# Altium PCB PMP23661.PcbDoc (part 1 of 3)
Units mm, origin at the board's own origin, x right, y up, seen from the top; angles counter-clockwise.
Board outline 209 x 127 mm, 4 copper layers (Top Layer, Layer 1, Layer 2, Bottom Layer), stack 1.787 mm thick; 235 components, 114 nets, 814 pads, 405 vias.
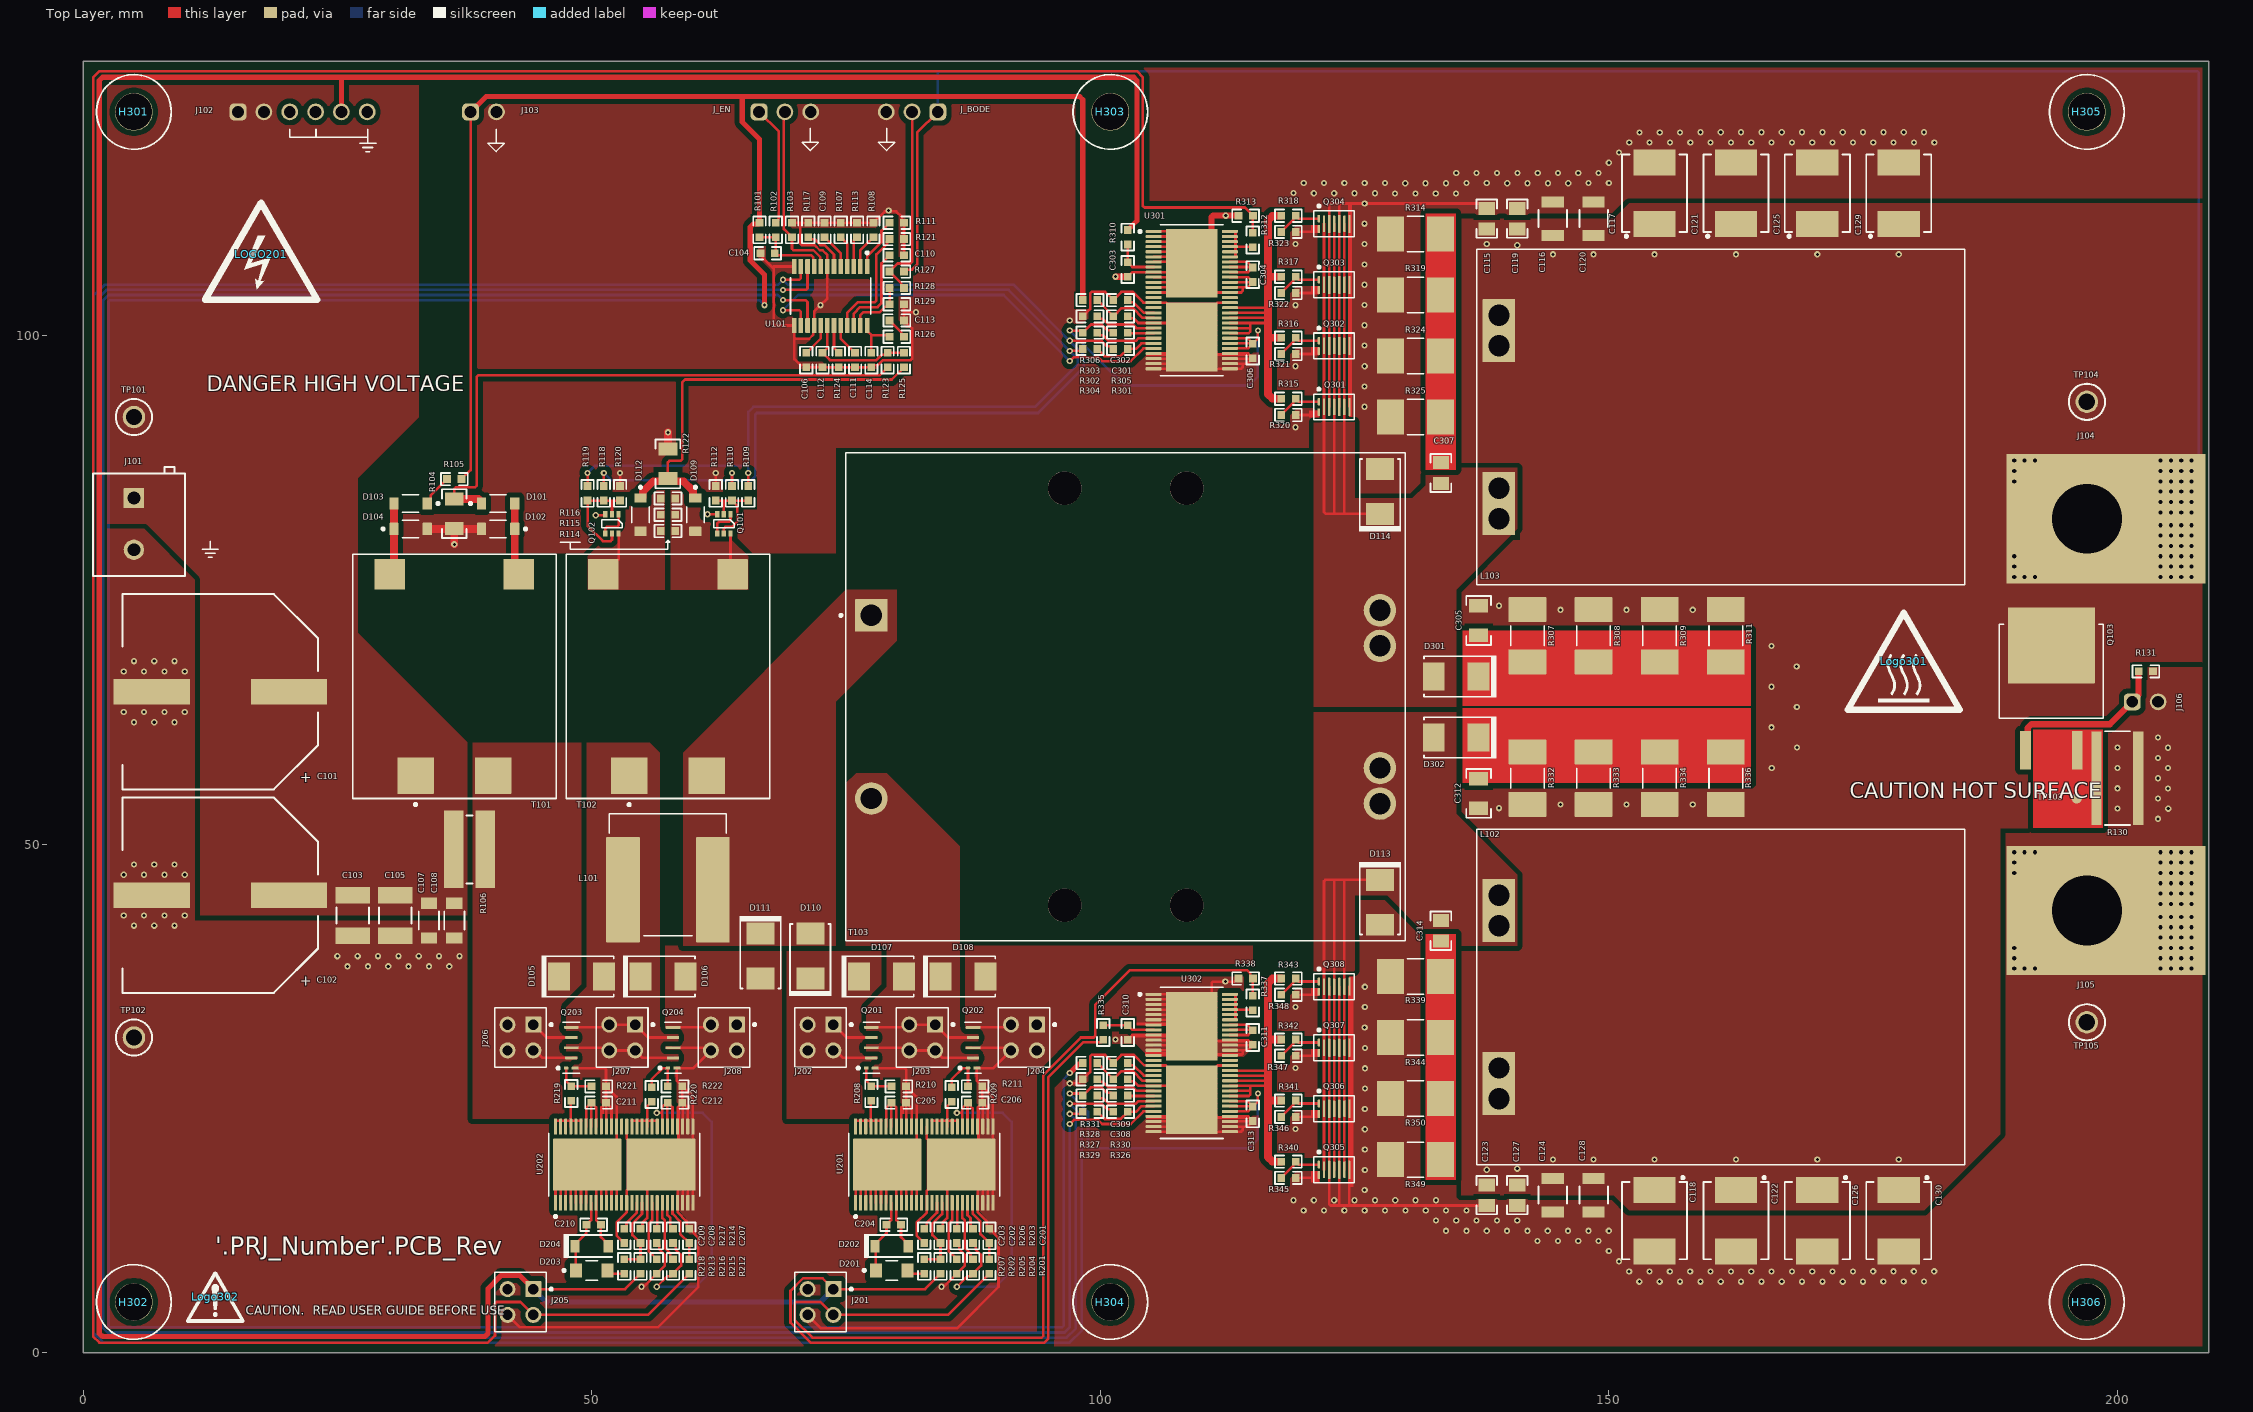
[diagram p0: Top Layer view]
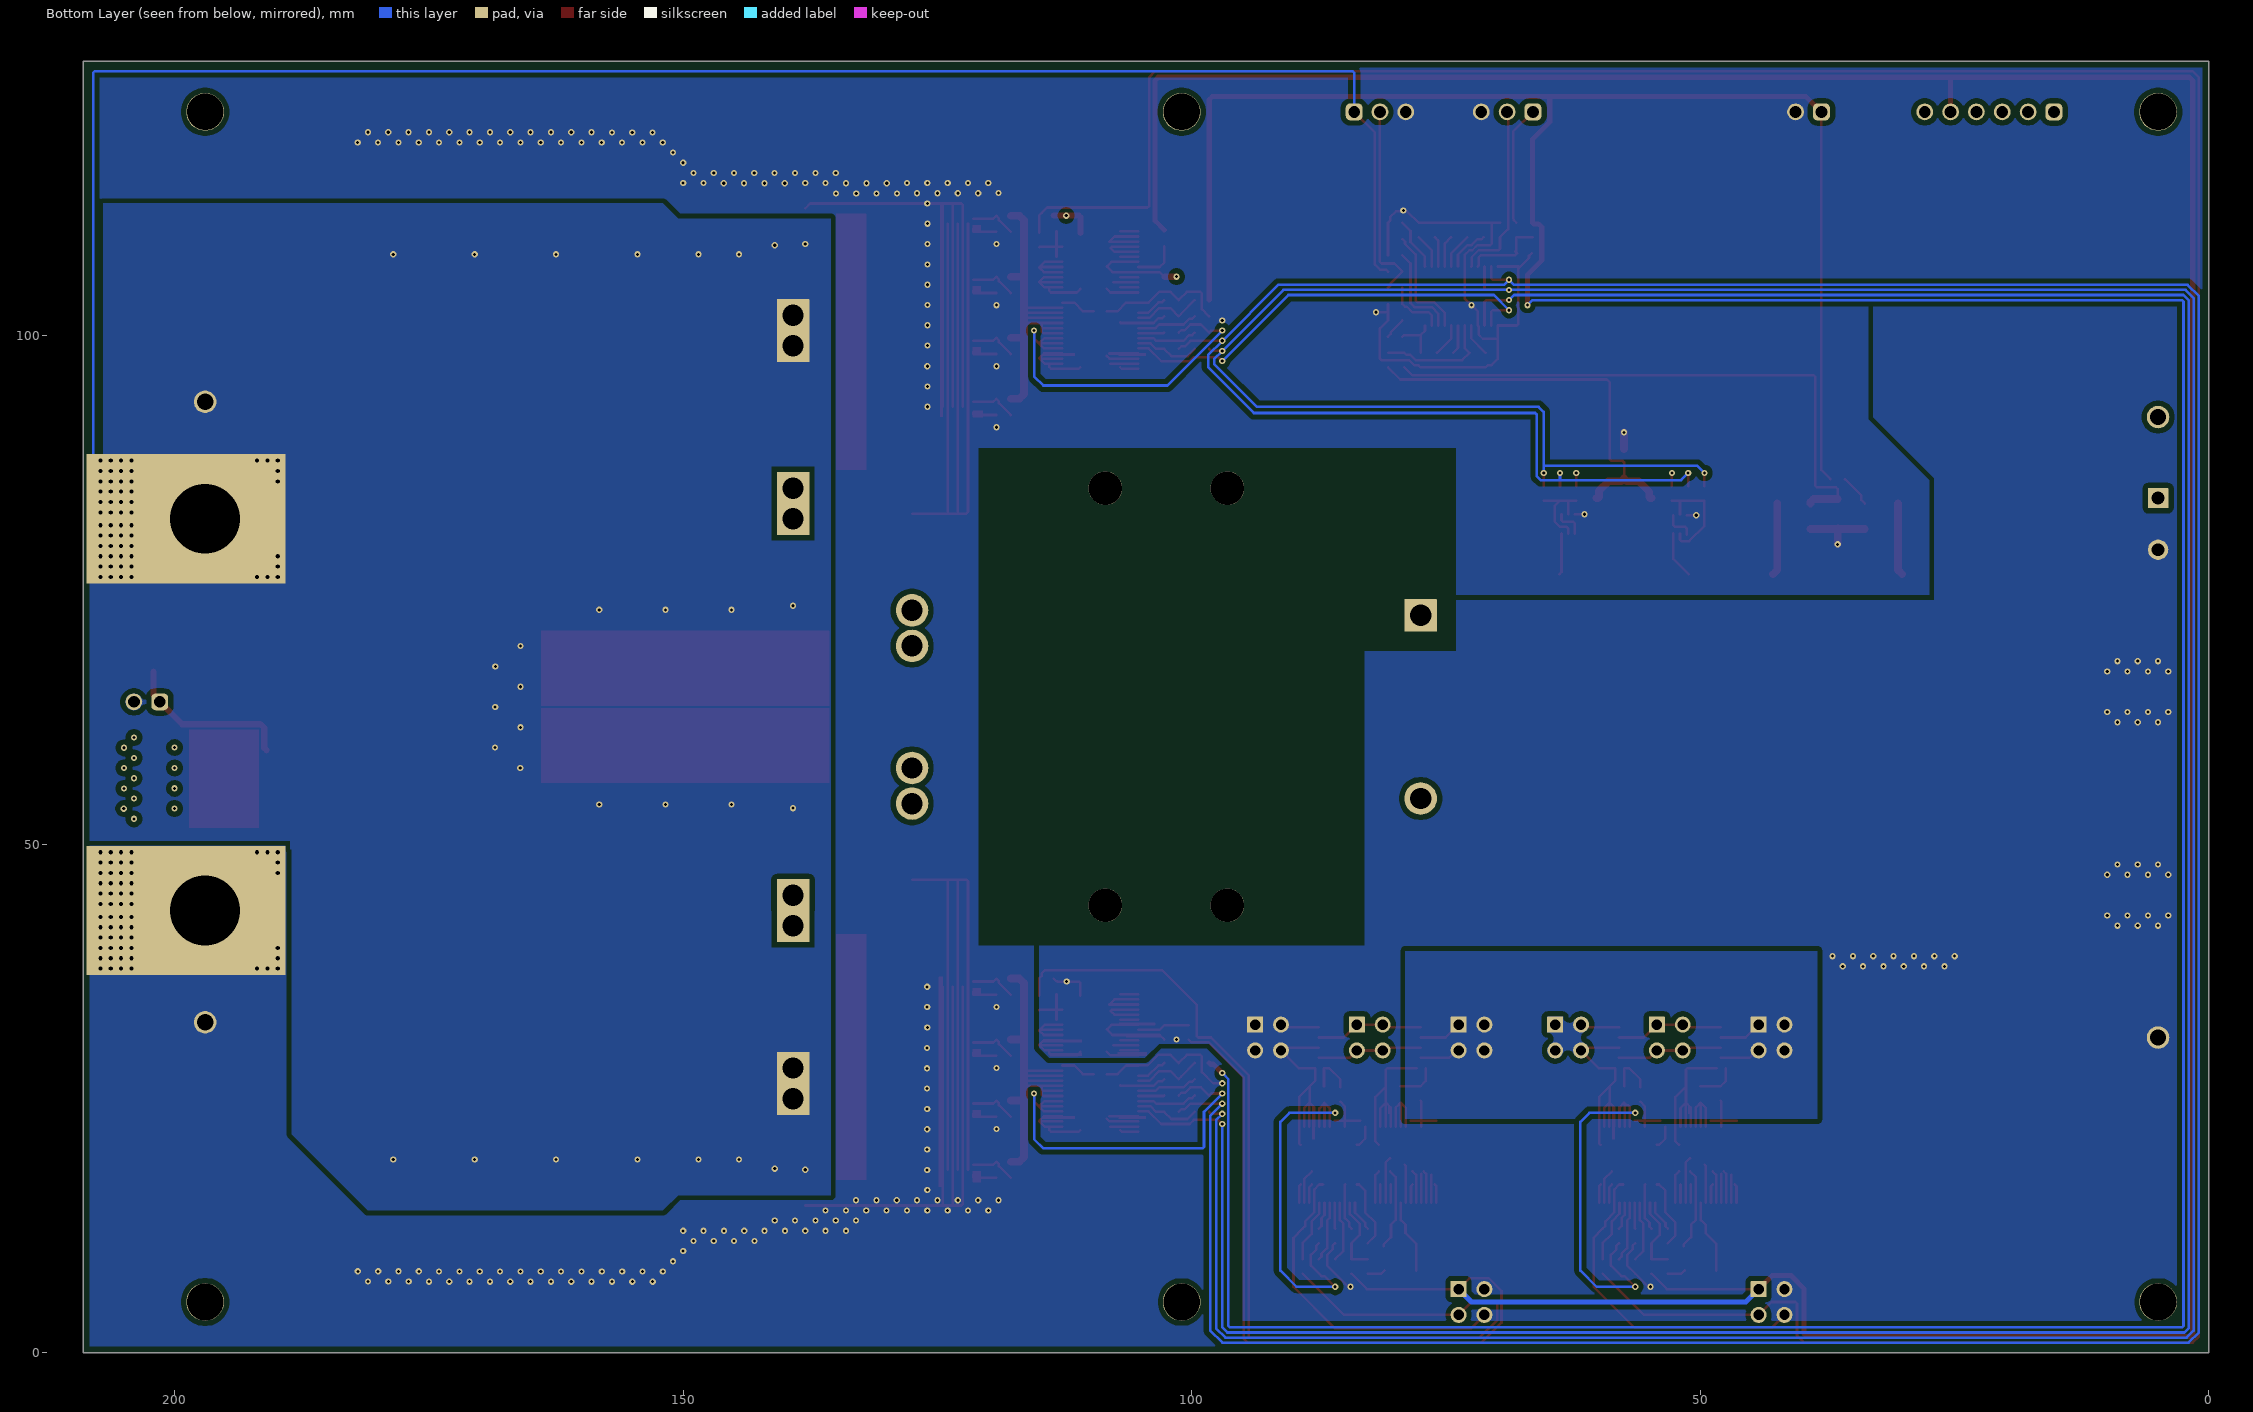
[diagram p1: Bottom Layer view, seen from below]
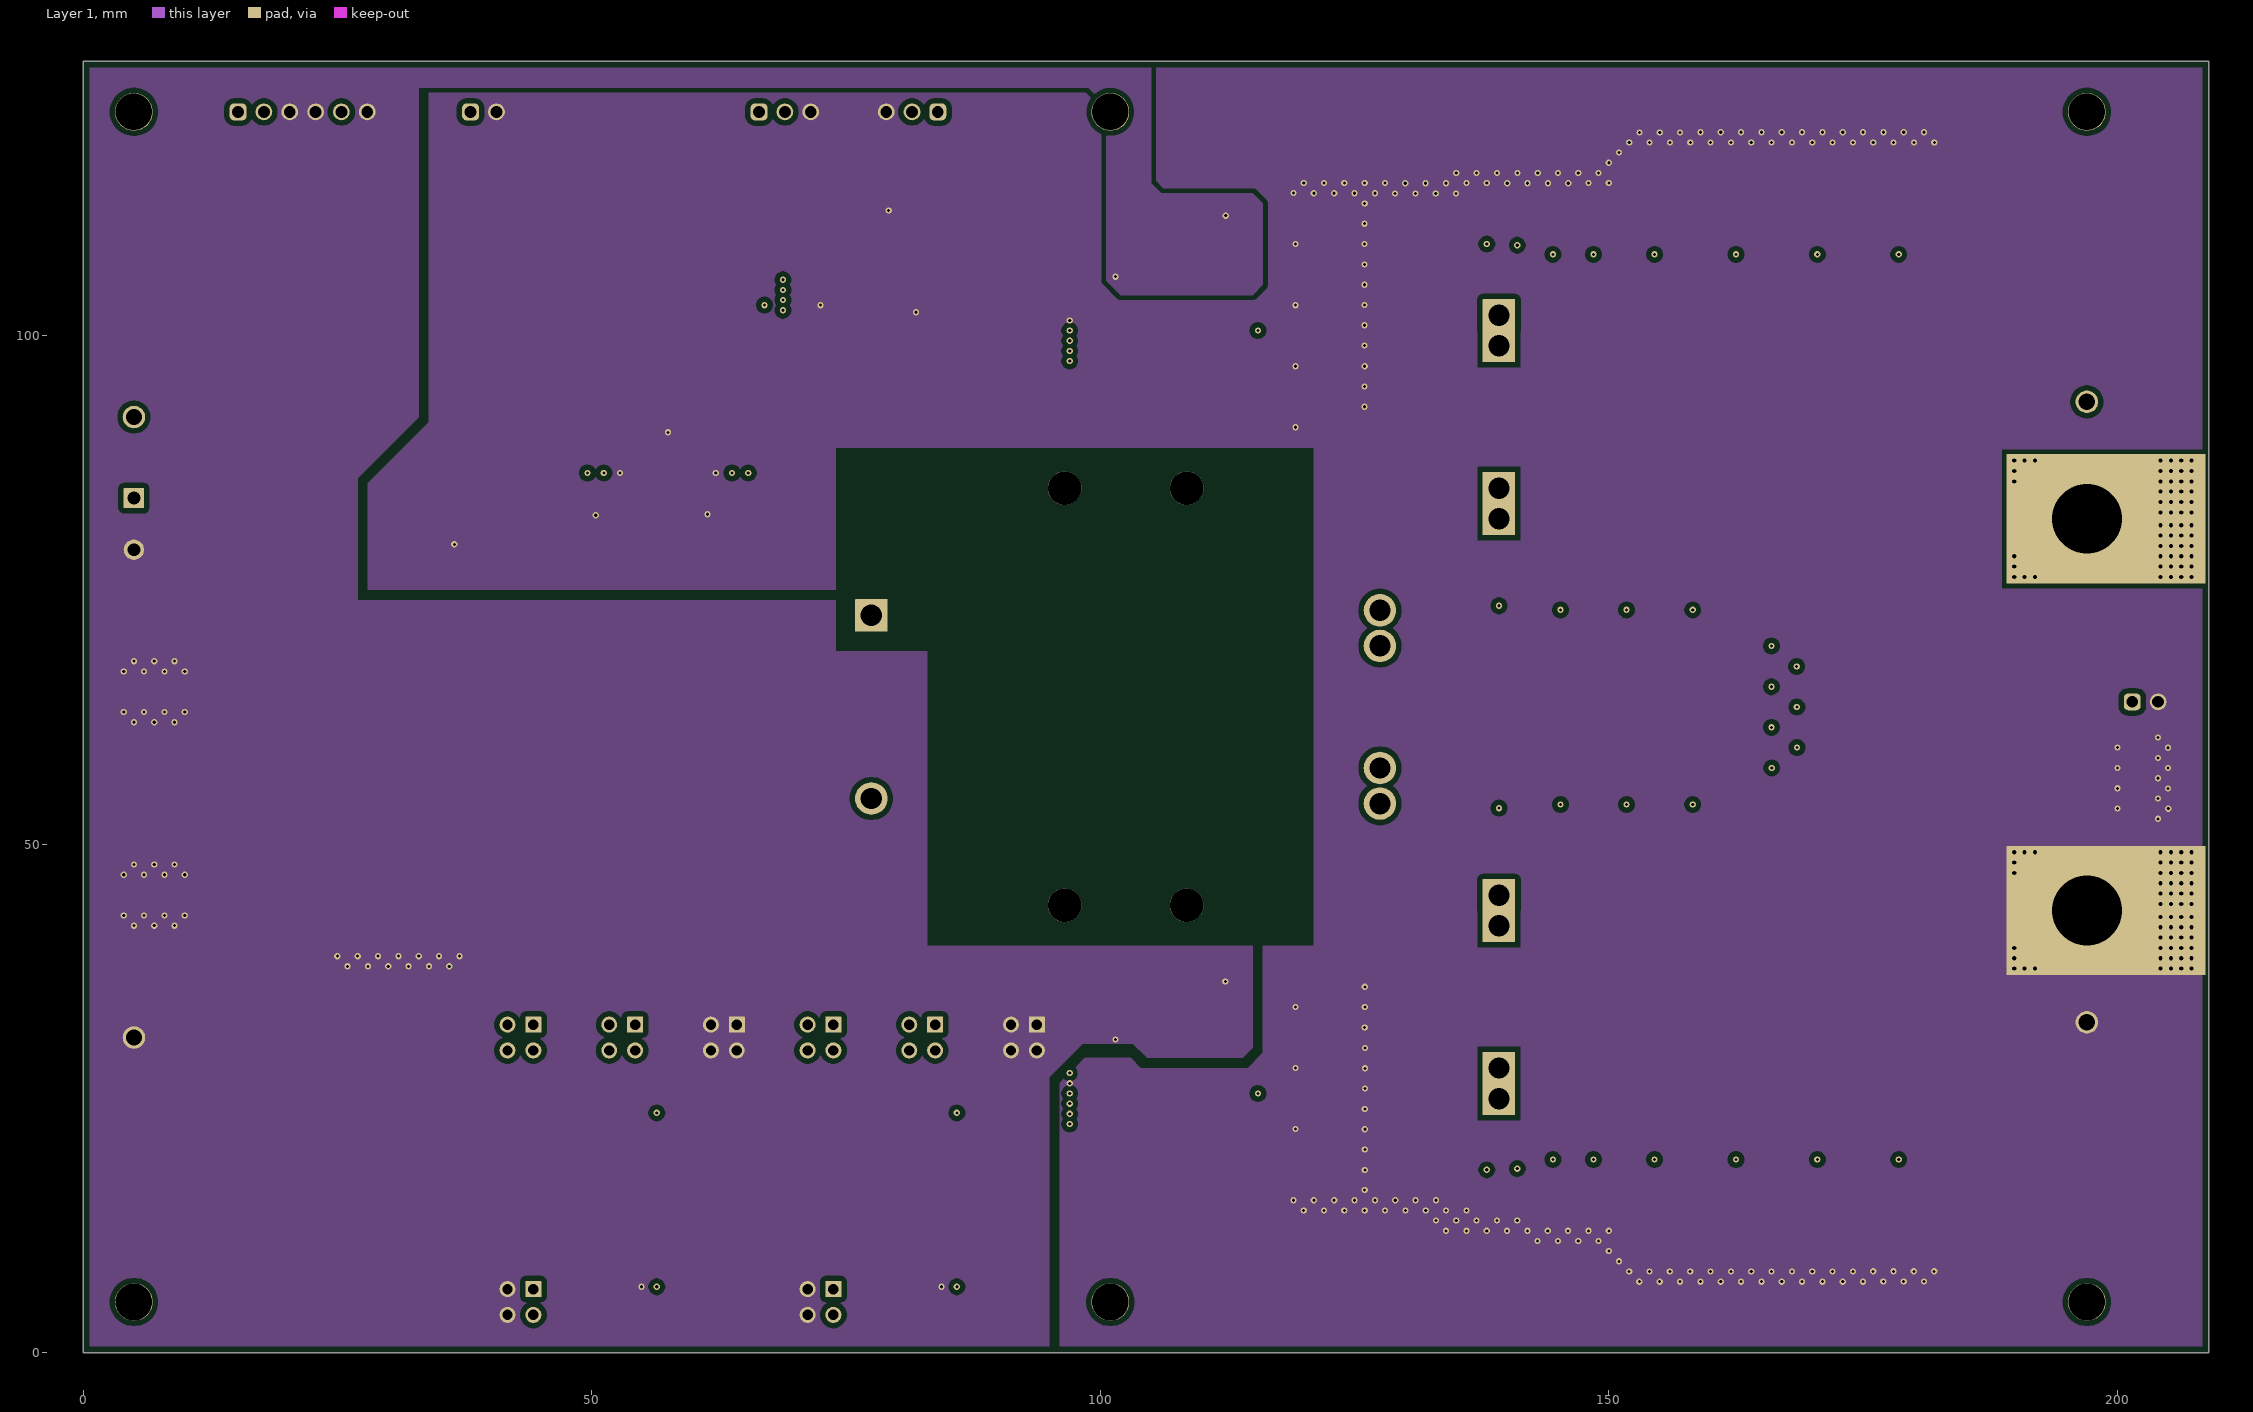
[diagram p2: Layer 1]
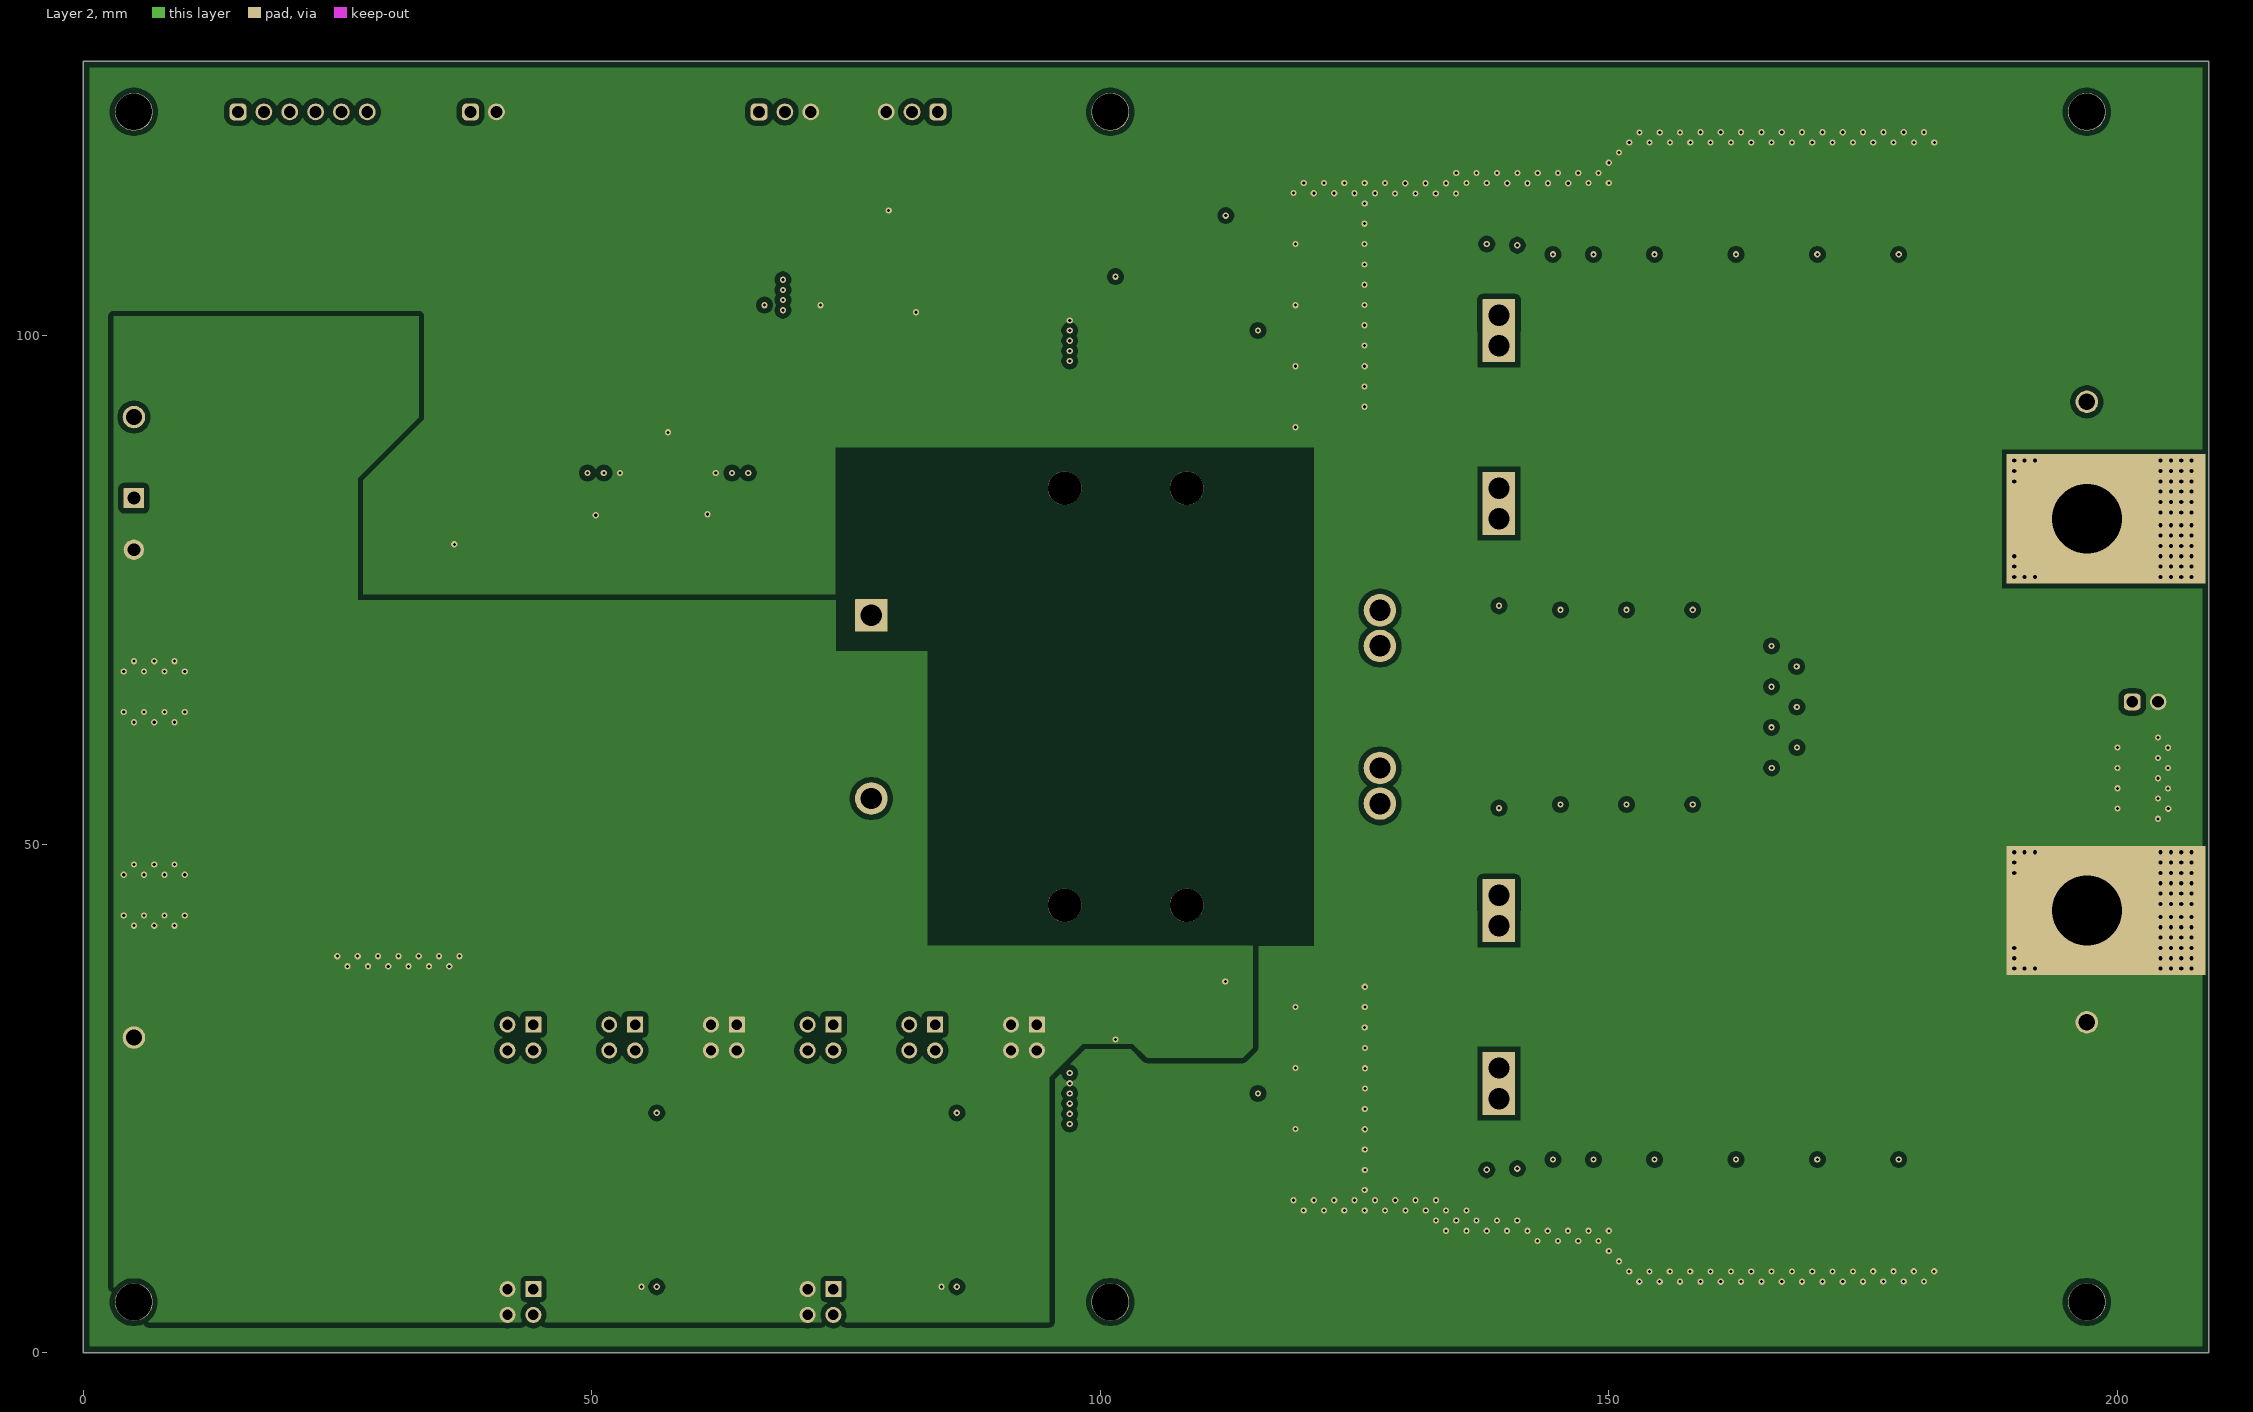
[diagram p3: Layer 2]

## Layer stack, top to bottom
Top Solder: solder mask 0.0102, Solder Resist, Dk 3.5
Top Layer: signal copper 0.0356
Dielectric 1: prepreg 0.0711, PP-006, Dk 4.1
Layer 1: signal copper 0.035
Dielectric1: core 1.5037, FR-4 High Tg, Dk 4.8
Layer 2: signal copper 0.035
Dielectric 2: prepreg 0.0711, PP-006, Dk 4.1
Bottom Layer: signal copper 0.0356
Bottom Solder: solder mask 0.0102, Solder Resist, Dk 3.5

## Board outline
0,0 0,127 209,127 209,0

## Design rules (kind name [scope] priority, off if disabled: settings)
AcuteAngle [All] p1: minimum=4.50000000000000E+0001 checktracksonly=FALSE
AssemblyTestPointUsage [All] p1: valid=2
BoardOutlineClearance BoardOutlineClearance_MountingHoles [OnCopper and InComponentClass('Mounting Holes')] p1: gap=0.635 ignorepadtopadclearanceinfootprint=FALSE
BoardOutlineClearance BoardOutlineClearance_Poly [OnCopper and InPoly] p2: gap=0.635 ignorepadtopadclearanceinfootprint=FALSE
BoardOutlineClearance [OnCopper and Not InComponentClass('Logo') and not InComponentClass('FiducialMark') and not InRegion(1000,500,4000,800)] p3: gap=0.635 ignorepadtopadclearanceinfootprint=FALSE
Clearance Clearance_2 [InNetClass('HV') vs Not InNetClass('HV')] p1: gap=1.524 ignorepadtopadclearanceinfootprint=FALSE
Clearance Clearance_1 [InNetClass('MV') vs Not InNetClass('MV')] p2: gap=0.762 ignorepadtopadclearanceinfootprint=FALSE
Clearance Clearance_Keepouts [((IsTrack Or IsArc) And Not InPoly) And IsFree and IsKeepOut vs ((IsTrack Or IsArc) And Not InPoly) And IsFree and IsKeepOut] p3: gap=0 ignorepadtopadclearanceinfootprint=FALSE
Clearance Clearance_BoardEdge_MountingHoles [OnCopper and InComponentClass('Mounting Holes') vs IsKeepOut] p4: gap=1.016 ignorepadtopadclearanceinfootprint=FALSE except(0: Arc-Hole Track-Hole SMDPad-Hole THPad-Hole Via-Hole Fill-Hole Poly-Hole Region-Hole Text-Hole)
Clearance Clearance_BoardEdge_Poly [OnCopper and InPoly vs IsKeepOut] p5: gap=1.27 ignorepadtopadclearanceinfootprint=FALSE except(0: Arc-Hole Track-Hole SMDPad-Hole THPad-Hole Via-Hole Fill-Hole Poly-Hole Region-Hole Text-Hole)
Clearance Clearance_BoardEdge [OnCopper and Not InComponentClass('Logo') and not InComponentClass('FiducialMark') and not InRegion(1000,500,4000,800) and Not IsKeepout vs IsKeepOut] p6: gap=1.27 ignorepadtopadclearanceinfootprint=FALSE
Clearance Clearance_Poly [InPolygon] p7: gap=0.508 ignorepadtopadclearanceinfootprint=FALSE except(0: Arc-Hole Track-Hole SMDPad-Hole THPad-Hole Via-Hole Fill-Hole Poly-Hole Region-Hole Text-Hole)
Clearance [All] p8: gap=0.152 ignorepadtopadclearanceinfootprint=FALSE
ComponentClearance ComponentClearance_MountingHoles_FiducialMarks [InComponentClass('Mounting Holes') vs InComponentClass('FiducialMark')] p1: gap=0.508 collisioncheckmode=3 verticalgap=0.254 showdistances=FALSE
ComponentClearance ComponentClearance_Shunt [InComponentClass('Header') vs InComponentClass('Shunt')] p2: gap=0 collisioncheckmode=3 verticalgap=0 showdistances=FALSE
ComponentClearance ComponentClearance_Logo [InComponentClass('Logo')] p3: gap=0.127 collisioncheckmode=3 verticalgap=0.254 showdistances=FALSE
ComponentClearance ComponentClearance_ScrewToNut [(HasFootprint('NY PMS 440 0025 PH')) vs (HasFootprint('Keystone_1902C'))] p4: gap=0.508 collisioncheckmode=3 verticalgap=2540 showdistances=FALSE
ComponentClearance ComponentClearance_MountingHoles [InComponentClass('Mounting Holes')] p5: gap=0.508 collisioncheckmode=3 verticalgap=0.254 showdistances=FALSE
ComponentClearance ComponentClearance_SmallPassives [HasFootprint('0201*') or HasFootprint('0402*') or HasFootprint('0508') or HasFootprint('0603*') or HasFootprint('0612') or HasFootprint('0805*') or HasFootprint('0815*') or HasFootprint('0830*') or HasFootprint('1206*') or HasFootprint('1210*') or HasFootprint('1808*') or HasFootprint('1812*') or HasFootprint('1825*') or HasFootprint('2010*') or HasFootprint('2220*') or HasFootprint('2225*') or HasFootprint('2512*') or HasFootprint('2728*') or HasFootprint('3518*') vs HasFootprint('0201*') or HasFootprint('0402*') or HasFootprint('0508') or HasFootprint('0603*') or HasFootprint('0612') or HasFootprint('0805*') or HasFootprint('0815*') or HasFootprint('0830*') or HasFootprint('1206*') or HasFootprint('1210*') or HasFootprint('1808*') or HasFootprint('1812*') or HasFootprint('1825*') or HasFootprint('2010*') or HasFootprint('2220*') or HasFootprint('2225*') or HasFootprint('2512*') or HasFootprint('2728*') or HasFootprint('3518*')] p6: gap=0.508 collisioncheckmode=3 verticalgap=0.508 showdistances=FALSE
ComponentClearance ComponentClearance_THtoSMT [IsThruComponent vs IsSMTComponent] p7: gap=0.254 collisioncheckmode=3 verticalgap=0.254 showdistances=FALSE
ComponentClearance ComponentClearance_THtoTH [IsThruComponent vs IsThruComponent] p8: gap=0.254 collisioncheckmode=3 verticalgap=0.254 showdistances=FALSE
ComponentClearance [All] p9: gap=0.254 collisioncheckmode=3 verticalgap=0.254 showdistances=FALSE
DiffPairsRouting [All] p1: maxlimit=2.54 minlimit=0.254 mostfreqgap=0.254 toplayer_minwidth=0.381 toplayer_maxwidth=0.381 toplayer_prefwidth=0.381 midlayer1_minwidth=0.381 midlayer1_maxwidth=0.381 midlayer1_prefwidth=0.381 midlayer2_minwidth=0.381 midlayer2_maxwidth=0.381 midlayer2_prefwidth=0.381 bottomlayer_minwidth=0.381 bottomlayer_maxwidth=0.381 bottomlayer_prefwidth=0.381 maxuncoupledlength=25.4
FabricationTestPointUsage TestPointUsage [All] p1: valid=2 allowmultiple=FALSE
FabricationTestpoint Testpoint [All] p1: side=3 testpointundercomponent=TRUE minsize=1.016 maxsize=2.54 preferedsize=1.524 minholesize=0 maxholesize=1.016 preferedholesize=0.813 testpointgrid=0.025 allowsidetop=TRUE allowsidebottom=TRUE usegrid=TRUE gridtolerance=0
FanoutControl Fanout_LCC [IsLCC] p1: bgadir=Out bgaviamode=Centered fanoutstyle=Auto fanoutdirection=Alternating viagrid=0.025 // Fanout_LCC (Default Rule)
FanoutControl Fanout_BGA [IsBGA] p2: bgadir=Out bgaviamode=Centered fanoutstyle=Auto fanoutdirection=Alternating viagrid=0.025 // Fanout_BGA (Default Rule)
FanoutControl Fanout_Default [All] p4: bgadir=Out bgaviamode=Centered fanoutstyle=Auto fanoutdirection=Alternating viagrid=0.025 // Fanout_Default (Default Rule)
FanoutControl Fanout_Small [(CompPinCount < 5)] p5: bgadir=Out bgaviamode=Centered fanoutstyle=Auto fanoutdirection=OutThenIn viagrid=0.025 // Fanout_Small (Default Rule)
Height [All] p1: minheight=0 maxheight=76.2 prefheight=12.7
HoleSize [All] p1: absolutevalues=TRUE maxlimit=6.375 minlimit=0.2 maxpercent=80.000 minpercent=20.000
MinimumAnnularRing MinimumAnnularRing_ThermalPadVias [IsVia and InAnyComponent] p1: minimumring=0.15
MinimumAnnularRing [All] p2: minimumring=0.15
MinimumSolderMaskSliver MinimumSolderMaskSliver_Logo [InComponentClass('Logo') vs InComponentClass('Logo')] p1: minsoldermaskwidth=0.018
MinimumSolderMaskSliver [All] p2: minsoldermaskwidth=0.1
PlaneConnect [All] p1: planeconnectstyle=Direct reliefexpansion=0.254 reliefentries=4 reliefconductorwidth=0.254 reliefairgap=0.254
PolygonConnect PolygonConnect_15 [All vs IsNamedPolygon('C109_2') Or  IsNamedPolygon('C107_2') Or  IsNamedPolygon('HV') Or  IsNamedPolygon('Q203_5') Or  IsNamedPolygon('C107_2') Or  IsNamedPolygon('HS') Or  IsNamedPolygon('Q201_5') Or  IsNamedPolygon('Q203_5') Or  IsNamedPolygon('C106_2') Or  IsNamedPolygon('C108_2') Or  IsNamedPolygon('Vout') Or  IsNamedPolygon('Q203_5') Or  IsNamedPolygon('C108_2') Or  IsNamedPolygon('C113_2') Or  IsNamedPolygon('Q203_5') Or  IsNamedPolygon('Q201_5') Or  IsNamedPolygon('C107_2') Or  IsNamedPolygon('C102_1') Or  IsNamedPolygon('SGND') Or  IsNamedPolygon('GND') Or  IsNamedPolygon('SGND') Or  IsNamedPolygon('GND') Or  IsNamedPolygon('IN+') Or  IsNamedPolygon('IN+') Or  IsNamedPolygon('Q201_5') Or  IsNamedPolygon('Q201_5') Or  IsNamedPolygon('SGND') Or  IsNamedPolygon('SGND') Or  IsNamedPolygon('Vout') Or  IsNamedPolygon('Vout') Or  IsNamedPolygon('IN+') Or  IsNamedPolygon('GND') Or  IsNamedPolygon('IN+') Or  IsNamedPolygon('GND')] p1: connectstyle=Direct reliefconductorwidth=0.254 reliefentries=4 polygonreliefangle="90 Angle" airgapwidth=0.254
PolygonConnect PolygonConnect_14 [All vs IsNamedPolygon('C106_2') Or  IsNamedPolygon('C107_2') Or  IsNamedPolygon('C107_2') Or  IsNamedPolygon('C107_2') Or  IsNamedPolygon('C102_1') Or  IsNamedPolygon('Q203_5') Or  IsNamedPolygon('Vout') Or  IsNamedPolygon('Q203_5') Or  IsNamedPolygon('Q203_5') Or  IsNamedPolygon('Q201_5') Or  IsNamedPolygon('C108_2') Or  IsNamedPolygon('Q203_5') Or  IsNamedPolygon('HS') Or  IsNamedPolygon('HV') Or  IsNamedPolygon('C108_2') Or  IsNamedPolygon('Q201_5') Or  IsNamedPolygon('C109_2') Or  IsNamedPolygon('Q201_5') Or  IsNamedPolygon('Q201_5') Or  IsNamedPolygon('C113_2')] p2: connectstyle=Direct reliefconductorwidth=0.254 reliefentries=4 polygonreliefangle="90 Angle" airgapwidth=0.254
PolygonConnect PolygonConnect_13 [All vs IsNamedPolygon('C102_1') Or  IsNamedPolygon('HV') Or  IsNamedPolygon('C107_2') Or  IsNamedPolygon('C109_2') Or  IsNamedPolygon('C107_2') Or  IsNamedPolygon('C108_2') Or  IsNamedPolygon('C106_2') Or  IsNamedPolygon('C108_2') Or  IsNamedPolygon('C113_2') Or  IsNamedPolygon('C107_2')] p3: connectstyle=Direct reliefconductorwidth=0.254 reliefentries=4 polygonreliefangle="90 Angle" airgapwidth=0.254
PolygonConnect PolygonConnect_12 [All vs IsNamedPolygon('C107_2') Or  IsNamedPolygon('C113_2') Or  IsNamedPolygon('C106_2') Or  IsNamedPolygon('C107_2') Or  IsNamedPolygon('C107_2') Or  IsNamedPolygon('C102_1')] p4: connectstyle=Direct reliefconductorwidth=0.254 reliefentries=4 polygonreliefangle="90 Angle" airgapwidth=0.254
PolygonConnect PolygonConnect_11 [All vs IsNamedPolygon('C106_2') Or  IsNamedPolygon('C102_1') Or  IsNamedPolygon('C107_2') Or  IsNamedPolygon('C107_2') Or  IsNamedPolygon('C107_2')] p5: connectstyle=Direct reliefconductorwidth=0.254 reliefentries=4 polygonreliefangle="90 Angle" airgapwidth=0.254
PolygonConnect PolygonConnect_10 [All vs IsNamedPolygon('C106_2')] p6: connectstyle=Direct reliefconductorwidth=0.254 reliefentries=4 polygonreliefangle="90 Angle" airgapwidth=0.254
PolygonConnect PolygonConnect_9 [All vs IsNamedPolygon('C11_1') Or  IsNamedPolygon('Vin') Or  IsNamedPolygon('Vin') Or  IsNamedPolygon('5V') Or  IsNamedPolygon('D6_2') Or  IsNamedPolygon('Q3_3') Or  IsNamedPolygon('GND2') Or  IsNamedPolygon('GND2') Or  IsNamedPolygon('GND') Or  IsNamedPolygon('Q3_4') Or  IsNamedPolygon('12V5') Or  IsNamedPolygon('GND') Or  IsNamedPolygon('12V5') Or  IsNamedPolygon('D3_1')] p7: connectstyle=Direct reliefconductorwidth=0.254 reliefentries=4 polygonreliefangle="90 Angle" airgapwidth=0.254
PolygonConnect PolygonConnect_8 [All vs IsNamedPolygon('C11_1') Or  IsNamedPolygon('Vin') Or  IsNamedPolygon('12V5') Or  IsNamedPolygon('Q3_3') Or  IsNamedPolygon('GND2') Or  IsNamedPolygon('GND2') Or  IsNamedPolygon('5V') Or  IsNamedPolygon('Q3_4') Or  IsNamedPolygon('12V5')] p8: connectstyle=Direct reliefconductorwidth=0.254 reliefentries=4 polygonreliefangle="90 Angle" airgapwidth=0.254
PolygonConnect PolygonConnect_7 [All vs IsNamedPolygon('GND2') Or  IsNamedPolygon('GND2') Or  IsNamedPolygon('5V') Or  IsNamedPolygon('12V5') Or  IsNamedPolygon('12V5') Or  IsNamedPolygon('C11_1')] p9: connectstyle=Direct reliefconductorwidth=0.254 reliefentries=4 polygonreliefangle="90 Angle" airgapwidth=0.254
PolygonConnect PolygonConnect_6 [All vs IsNamedPolygon('GND2') Or  IsNamedPolygon('SGND') Or  IsNamedPolygon('GND1') Or  IsNamedPolygon('C901_1') Or  IsNamedPolygon('SGND') Or  IsNamedPolygon('GND2') Or  IsNamedPolygon('GND1')] p10: connectstyle=Direct reliefconductorwidth=0.254 reliefentries=4 polygonreliefangle="90 Angle" airgapwidth=0.254
PolygonConnect PolygonConnect_5 [All vs IsNamedPolygon('GND1') Or  IsNamedPolygon('GND1')] p11: connectstyle=Direct reliefconductorwidth=0.254 reliefentries=4 polygonreliefangle="90 Angle" airgapwidth=0.254
PolygonConnect PolygonConnect_4 [All vs IsNamedPolygon('C21_1') Or  IsNamedPolygon('C5_1') Or  IsNamedPolygon('C12_2') Or  IsNamedPolygon('C2_2') Or  IsNamedPolygon('C13_1') Or  IsNamedPolygon('C28_1') Or  IsNamedPolygon('C6_1') Or  IsNamedPolygon('GND') Or  IsNamedPolygon('GND2') Or  IsNamedPolygon('C14_1') Or  IsNamedPolygon('C13_1') Or  IsNamedPolygon('Q1_3') Or  IsNamedPolygon('C14_1') Or  IsNamedPolygon('C5_1') Or  IsNamedPolygon('GND2') Or  IsNamedPolygon('C28_1') Or  IsNamedPolygon('D5_2') Or  IsNamedPolygon('D6_2') Or  IsNamedPolygon('D2_1') Or  IsNamedPolygon('C12_2') Or  IsNamedPolygon('D2_1') Or  IsNamedPolygon('C4_1') Or  IsNamedPolygon('C4_1') Or  IsNamedPolygon('C2_2') Or  IsNamedPolygon('GND') Or  IsNamedPolygon('C33_1') Or  IsNamedPolygon('C9_1')] p12: connectstyle=Direct reliefconductorwidth=0.254 reliefentries=4 polygonreliefangle="90 Angle" airgapwidth=0.254
PolygonConnect PolygonConnect_3 [All vs IsNamedPolygon('C28_1') Or  IsNamedPolygon('C12_2') Or  IsNamedPolygon('C28_1') Or  IsNamedPolygon('C9_1') Or  IsNamedPolygon('D5_2') Or  IsNamedPolygon('C12_2') Or  IsNamedPolygon('C2_2') Or  IsNamedPolygon('C14_1') Or  IsNamedPolygon('C4_1') Or  IsNamedPolygon('C14_1') Or  IsNamedPolygon('D6_2') Or  IsNamedPolygon('GND2') Or  IsNamedPolygon('Q1_3') Or  IsNamedPolygon('C5_1') Or  IsNamedPolygon('D2_1') Or  IsNamedPolygon('C4_1') Or  IsNamedPolygon('C13_1') Or  IsNamedPolygon('C5_1') Or  IsNamedPolygon('C13_1') Or  IsNamedPolygon('C33_1') Or  IsNamedPolygon('D2_1') Or  IsNamedPolygon('GND') Or  IsNamedPolygon('GND') Or  IsNamedPolygon('GND2') Or  IsNamedPolygon('C2_2') Or  IsNamedPolygon('C6_1') Or  IsNamedPolygon('C21_1')] p13: connectstyle=Direct reliefconductorwidth=0.254 reliefentries=4 polygonreliefangle="90 Angle" airgapwidth=0.254
PolygonConnect PolygonConnect_2 [All vs IsNamedPolygon('C21_1') Or  IsNamedPolygon('C4_1') Or  IsNamedPolygon('D5_2') Or  IsNamedPolygon('C5_1') Or  IsNamedPolygon('C14_1') Or  IsNamedPolygon('C13_1') Or  IsNamedPolygon('C4_1') Or  IsNamedPolygon('C33_1') Or  IsNamedPolygon('C12_2') Or  IsNamedPolygon('D2_1') Or  IsNamedPolygon('C2_2') Or  IsNamedPolygon('C28_1') Or  IsNamedPolygon('C12_2') Or  IsNamedPolygon('D2_1') Or  IsNamedPolygon('C5_1') Or  IsNamedPolygon('Q1_3') Or  IsNamedPolygon('GND') Or  IsNamedPolygon('D6_2') Or  IsNamedPolygon('C6_1') Or  IsNamedPolygon('C2_2') Or  IsNamedPolygon('C14_1') Or  IsNamedPolygon('C28_1') Or  IsNamedPolygon('C13_1') Or  IsNamedPolygon('C9_1') Or  IsNamedPolygon('GND')] p14: connectstyle=Direct reliefconductorwidth=0.254 reliefentries=4 polygonreliefangle="90 Angle" airgapwidth=0.254
PolygonConnect PolygonConnect_1 [All vs IsNamedPolygon('C28_1') Or  IsNamedPolygon('D5_2') Or  IsNamedPolygon('C5_1') Or  IsNamedPolygon('C5_1') Or  IsNamedPolygon('D2_1') Or  IsNamedPolygon('C21_1') Or  IsNamedPolygon('C9_1') Or  IsNamedPolygon('C4_1') Or  IsNamedPolygon('C14_1') Or  IsNamedPolygon('C28_1') Or  IsNamedPolygon('C6_1') Or  IsNamedPolygon('C12_2') Or  IsNamedPolygon('C33_1') Or  IsNamedPolygon('C4_1') Or  IsNamedPolygon('C13_1') Or  IsNamedPolygon('C12_2') Or  IsNamedPolygon('D6_2') Or  IsNamedPolygon('C2_2') Or  IsNamedPolygon('C14_1') Or  IsNamedPolygon('D2_1') Or  IsNamedPolygon('C2_2') Or  IsNamedPolygon('C13_1')] p15: connectstyle=Direct reliefconductorwidth=0.254 reliefentries=4 polygonreliefangle="90 Angle" airgapwidth=0.254
PolygonConnect [All] p16: connectstyle=Direct reliefconductorwidth=0.254 reliefentries=4 polygonreliefangle="90 Angle" airgapwidth=0.254
RoutingVias ThermalPadVias [IsVia and InAnyComponent] p1: holewidth=0.3 width=0.5 viastyle="Through Hole" minholewidth=0.13 minwidth=0.15 maxholewidth=1 maxwidth=2
RoutingVias [All] p2: holewidth=0.3 width=0.4 viastyle="Through Hole" minholewidth=0.13 minwidth=0.15 maxholewidth=3 maxwidth=6.3
SilkToBoardRegionClearance [Not ((IsComment or IsDesignator) And (Hide <> 'False')) and not InRegion(1000,500,4000,800)] p1:
SilkToSilkClearance SilkToSilkClearance_Pb-FreeLogo [(HasFootprint('Pb-Free_Overlay_Medium') OR HasFootprint('Pb-Free_Overlay_Small')) vs (HasFootprint('Pb-Free_Overlay_Medium') OR HasFootprint('Pb-Free_Overlay_Small'))] p1: silktosilkclearance=0
SilkToSilkClearance [All] p2: silktosilkclearance=0.102
SilkToSolderMaskClearance SilkToComponentPadClearance [IsPad and InAnycomponent] p1: minsilkscreentomaskgap=0.127 clearancetoexposedcopper=TRUE
SilkToSolderMaskClearance "Silk to Solder Mask Opening" [All] p2: minsilkscreentomaskgap=0.102 clearancetoexposedcopper=FALSE
SolderMaskExpansion [All] p1: expansion=0.05 istentingtop=FALSE
SupplyNets "Schematic Supply Nets_7" [InNet('HV')] p1: voltage=0.000
SupplyNets "Schematic Supply Nets_6" [InNet('+12Vs')] p2: voltage=0.000
SupplyNets "Schematic Supply Nets_5" [InNet('PGND')] p3: voltage=0.000
SupplyNets "Schematic Supply Nets_4" [InNet('SGND')] p4: voltage=0.000
SupplyNets "Schematic Supply Nets_1" [InNet('VOUT')] p5: voltage=0.000
SupplyNets "Schematic Supply Nets" [InNet('+12Vp')] p6: voltage=0.000
Width [All] p1: maxlimit=2.54 minlimit=0.152 preferedwidth=0.254 checkconnectedcopper=TRUE
14 further rules are at their usual default settings.

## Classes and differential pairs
component class "PMP23661_Secondary Drivers": !PCB201 C303 C304 C305 C307 C308 C310 C313 D301 D302 H301 H302 H305 H306 Logo301 Logo302 Q301 Q302 Q304 Q308 R303 R305 R306 R310 R312 R314 R316 R317 R321 R324 R326 R327 R330 R334 R338 R339 R342 R345 R347 R349 U301 U302
component class "PMP23661_Primary Drivers": C201 C205 C207 C211 C212 D201 D202 D203 D204 J201 J203 J206 J208 LOGO201 Q201 Q202 Q204 R202 R203 R208 R210 R212 R216 R217 R218 R220 R221 R222 U201 U202
component class Header: J101 J103 J106 J_BODE J_EN

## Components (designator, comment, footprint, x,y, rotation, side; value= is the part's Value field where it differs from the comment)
C101 "EEV-EB2D470SM" EB_K16 13.5,65 r180 top value=47uF
C102 "EEV-EB2D470SM" EB_K16 13.5,45 r180 top value=47uF
C103 "18122C105KAT2A" 1812_280 26.5,43 r270 top value=1uF
C104 "GRM188R71E105KA12D" 0603_HV 67.3,108.1 r180 top value=1uF
C105 "18122C105KAT2A" 1812_280 30.7,43 r270 top value=1uF
C106 "GRM188Z71C225KE43" 0603_HV 71.1,97.6 r90 top value=2.2uF
C107 "GRM31CR72D104KW03L" 1206_180 34,42.5 r270 top value=0.1uF
C108 "GRM31CR72D104KW03L" 1206_180 36.5,42.5 r270 top value=0.1uF
C109 "GRM188R71E562KA01D" 0603_HV 72.9,110.4 r270 top value=5600pF
C110 "GCM188R71E104KA57D" 0603_HV 80,107.9 r0 top value=0.1uF
C111 "GCM188R71C474KA55D" 0603_HV 75.9,97.6 r90 top value=0.47uF
C112 "GCM1885C2A100JA16D" 0603_HV 72.7,97.6 r270 top value=10pF
C113 "GRM188R71E123KA01D" 0603_HV 80,101.5 r0 top value=0.012uF
C114 "GRM188R71H471KA01D" 0603_HV 77.5,97.6 r270 top value=470pF
C115 "C0805C105K3RACTU" 0805_HV 138,111.5 r90 top value=1uF
C116 "C1210C106K3RACTU" 1210_280 144.5,111.5 r90 top value=10uF
C117 "T495E107K025ATE100" 7360-38 154.5,114 r90 top value=100uF
C118 "T495E107K025ATE100" 7360-38 154.5,13 r270 top value=100uF
C119 "C0805C105K3RACTU" 0805_HV 141,111.5 r90 top value=1uF
C120 "C1210C106K3RACTU" 1210_280 148.5,111.5 r90 top value=10uF
C121 "T495E107K025ATE100" 7360-38 162.5,114 r90 top value=100uF
C122 "T495E107K025ATE100" 7360-38 162.5,13 r270 top value=100uF
C123 "C0805C105K3RACTU" 0805_HV 138,15.5 r270 top value=1uF
C124 "C1210C106K3RACTU" 1210_280 144.5,15.5 r270 top value=10uF
C125 "T495E107K025ATE100" 7360-38 170.5,114 r90 top value=100uF
C126 "T495E107K025ATE100" 7360-38 170.5,13 r270 top value=100uF
C127 "C0805C105K3RACTU" 0805_HV 141,15.5 r270 top value=1uF
C128 "C1210C106K3RACTU" 1210_280 148.5,15.5 r270 top value=10uF
C129 "T495E107K025ATE100" 7360-38 178.5,114 r90 top value=100uF
C130 "T495E107K025ATE100" 7360-38 178.5,13 r270 top value=100uF
C201 "GRM1885C1H101JA01D" 0603_HV 89.1,11.5 r90 top value=100pF
C202 "GRM188R71E105KA12D" 0603_HV 84.3,11.5 r90 top value=1uF
C203 "GRM188R71E105KA12D" 0603_HV 82.7,11.5 r90 top value=1uF
C204 "C0603C104K5RACAUTO" 0603_HV 79.7,12.6 r180 top value=0.1uF
C205 "GRM188R71E105KA12D" 0603_HV 80.2,24.6 r180 top value=1uF
C206 "GRM188Z71C225KE43" 0603_HV 87.7,24.6 r180 top value=2.2uF
C207 "GRM1885C1H101JA01D" 0603_HV 59.6,11.5 r270 top value=100pF
C208 "GRM188R71E105KA12D" 0603_HV 54.8,11.5 r90 top value=1uF
C209 "GRM188R71E105KA12D" 0603_HV 53.2,11.5 r90 top value=1uF
C210 "C0603C104K5RACAUTO" 0603_HV 50.2,12.6 r180 top value=0.1uF
C211 "GRM188R71E105KA12D" 0603_HV 50.7,24.6 r180 top value=1uF
C212 "GRM188Z71C225KE43" 0603_HV 58.2,24.6 r180 top value=2.2uF
C301 "GRM188R71E105KA12D" 0603_HV 102,101.9 r0 top value=1uF
C302 "GRM188R71E105KA12D" 0603_HV 102,103.5 r0 top value=1uF
C303 "C0603C104K5RACAUTO" 0603_HV 102.7,106.5 r90 top value=0.1uF
C304 "GRM188Z71C225KE43" 0603_HV 115,106 r90 top value=2.2uF
C305 "GRM319R72A104KA01D" 1206 137.2,72 r90 top value=0.1uF
C306 "GRM188Z71C225KE43" 0603_HV 115,98.5 r90 top value=2.2uF
C307 "GRM2165C2A122JA01D" 0805_HV 133.5,86.5 r90 top value=1200pF
C308 "GRM188R71E105KA12D" 0603_HV 102,26.9 r0 top value=1uF
C309 "GRM188R71E105KA12D" 0603_HV 102,28.5 r0 top value=1uF
C310 "C0603C104K5RACAUTO" 0603_HV 102.7,31.5 r90 top value=0.1uF
C311 "GRM188Z71C225KE43" 0603_HV 115,31 r90 top value=2.2uF
C312 "GRM319R72A104KA01D" 1206 137.2,55 r270 top value=0.1uF
C313 "GRM188Z71C225KE43" 0603_HV 115,23.5 r90 top value=2.2uF
C314 "GRM2165C2A122JA01D" 0805_HV 133.5,41.5 r270 top value=1200pF
D101 "BAT46GWJ" FP-BAT46GWJ_SOD-123-MFG 40.8,83.5 r0 top
D102 "BAT46GWJ" FP-BAT46GWJ_SOD-123-MFG 40.8,81 r180 top
D103 "BAT46GWJ" FP-BAT46GWJ_SOD-123-MFG 32.2,83.5 r180 top
D104 "BAT46GWJ" FP-BAT46GWJ_SOD-123-MFG 32.2,81 r0 top
D105 "MBRS3200T3G" SMB 49,37 r0 top value=200V
D106 "MBRS3200T3G" SMB 57,37 r0 top value=200V
D107 "MBRS3200T3G" SMB 78.5,37 r0 top value=200V
D108 "MBRS3200T3G" SMB 86.5,37 r0 top value=200V
D109 "BAT46GWJ" FP-BAT46GWJ_SOD-123-MFG 60.2,82.4 r270 top
D110 "MBRS3200T3G" SMB 71.5,39 r90 top value=200V
D111 "MBRS3200T3G" SMB 66.6,39 r270 top value=200V
D112 "BAT46GWJ" FP-BAT46GWJ_SOD-123-MFG 54.8,82.4 r270 top
D113 "MBRS1100T3G" SMB 127.5,44.3 r270 top value=100V
D114 "MBRS1100T3G" SMB 127.5,84.7 r90 top value=100V
D201 "SS1H20LW" FP-SS1H20LW_SOD-123W-MFG 79.5,8.1 r0 top
D202 "MMSZ5243B-7-F" SOD-123 79.5,10.5 r0 top value=13V
D203 "SS1H20LW" FP-SS1H20LW_SOD-123W-MFG 50,8.1 r0 top
D204 "MMSZ5243B-7-F" SOD-123 50,10.5 r0 top value=13V
D301 "MBRS1100T3G" SMB 135,66.5 r180 top value=100V
D302 "MBRS1100T3G" SMB 135,60.5 r180 top value=100V
H301 "4820" KEYSTONE_4820 5,122 r0 top
H302 "4820" KEYSTONE_4820 5,5 r0 top
H303 "4820" KEYSTONE_4820 101,122 r0 top
H304 "4820" KEYSTONE_4820 101,5 r0 top
H305 "4820" KEYSTONE_4820 197,122 r0 top
H306 "4820" KEYSTONE_4820 197,5 r0 top
J101 "ED120/2DS" On-Shore_ED120_2DS 5,81.5 r270 top
J102 "61300611121" WURTH_61300611121 21.59,122 r0 top
J103 "61300211121" WURTH_61300211121 39.37,122 r0 top
J104 "CXS70-14-C" Panduit_CXS70-14-C 197,82 r180 top
J105 "CXS70-14-C" Panduit_CXS70-14-C 197,43.5 r180 top
J106 "61300211121" WURTH_61300211121 202.73,64 r0 top
J201 "SSQ-102-02-G-D" FP-SSQ-102-02-G-D_CONN_RCPT_4-MFG 72.5,5 r90 top
J202 "SSQ-102-02-G-D" FP-SSQ-102-02-G-D_CONN_RCPT_4-MFG 72.5,31 r90 top
J203 "SSQ-102-02-G-D" FP-SSQ-102-02-G-D_CONN_RCPT_4-MFG 82.5,31 r90 top
J204 "SSQ-102-02-G-D" FP-SSQ-102-02-G-D_CONN_RCPT_4-MFG 92.5,31 r90 top
J205 "SSQ-102-02-G-D" FP-SSQ-102-02-G-D_CONN_RCPT_4-MFG 43,5 r90 top
J206 "SSQ-102-02-G-D" FP-SSQ-102-02-G-D_CONN_RCPT_4-MFG 43,31 r90 top
J207 "SSQ-102-02-G-D" FP-SSQ-102-02-G-D_CONN_RCPT_4-MFG 53,31 r90 top
J208 "SSQ-102-02-G-D" FP-SSQ-102-02-G-D_CONN_RCPT_4-MFG 63,31 r90 top
J_BODE "61300311121" WURTH_61300311121 81.5,122 r180 top
J_EN "61300311121" WURTH_61300311121 69,122 r0 top
L101 "1212VS-111MED" FP-1212VS-111MED_SMT_IND_11MM5_12MM0-MFG 57.5,47 r0 top value=117nH
L102 "64192R00" FP-64192R00_PTH_IND_48MM0_33MM0-MFG 161,35 r0 top value=2uH
L103 "64192R00" FP-64192R00_PTH_IND_48MM0_33MM0-MFG 161,92 r0 top value=2uH
LOGO201 "DANGER HIGH VOLTAGE" IEC_HighVoltage_Medium 17.5,108 r0 top
Logo301 "CAUTION HOT SURFACE" IEC_HotSurface_Medium 179,68 r0 top
Logo302 "CAUTION.  READ USER GUIDE BEFORE USE" IEC_Caution_Small 13,5.5 r0 top
Q101 "2N7002DW" SOT-363 63,81.5 r270 top value=60V
Q102 "2N7002DW" SOT-363 52,81.5 r270 top value=60V
Q103 "CSD18511KTT" KTT0002A-MFG 193.5,67 r0 top
Q201 "EPC2215" FP-EPC2215_LGA6-MFG 77.5,30 r90 top
Q202 "EPC2215" FP-EPC2215_LGA6-MFG 87.5,30 r90 top
Q203 "EPC2215" FP-EPC2215_LGA6-MFG 48,30 r90 top
Q204 "EPC2215" FP-EPC2215_LGA6-MFG 58,30 r90 top
Q301 "EPC2088" FP-EPC2088_LGA8-MFG 123,93 r0 top
Q302 "EPC2088" FP-EPC2088_LGA8-MFG 123,99 r0 top
Q303 "EPC2088" FP-EPC2088_LGA8-MFG 123,105 r0 top
Q304 "EPC2088" FP-EPC2088_LGA8-MFG 123,111 r0 top
Q305 "EPC2088" FP-EPC2088_LGA8-MFG 123,18 r0 top
Q306 "EPC2088" FP-EPC2088_LGA8-MFG 123,24 r0 top
Q307 "EPC2088" FP-EPC2088_LGA8-MFG 123,30 r0 top
Q308 "EPC2088" FP-EPC2088_LGA8-MFG 123,36 r0 top
R101 "CRCW06030000Z0EA" 0603_HV 66.5,110.4 r90 top value=0
R102 "CRCW060349K9FKEA" 0603_HV 68.1,110.4 r90 top value=49.9k
R103 "CRCW060349K9FKEA" 0603_HV 69.7,110.4 r90 top value=49.9k
R104 "CRCW12061R69FKEA" 1206 36.5,82.5 r90 top value=1.69
R105 "CRCW06030000Z0EA" 0603_HV 36.5,85.9 r180 top value=0
R106 "RCL12250000Z0EG" 2512_WIDE_VISHAY 38,49.5 r180 top value=0
R107 "CRCW060349K9FKEA" 0603_HV 74.5,110.4 r90 top value=49.9k
R108 "CRCW0603147KFKEA" 0603_HV 77.7,110.4 r270 top value=147k
R109 "CRCW06030000Z0EA" 0603_HV 65.4,84.5 r90 top value=0
R110 "CRCW06030000Z0EA" 0603_HV 63.8,84.5 r90 top value=0
R111 "CRCW0603348KFKEA" 0603_HV 80,111.1 r180 top value=348k
R112 "CRCW060310K0FKEA" 0603_HV 62.2,84.5 r270 top value=10.0k
R113 "CRCW060375K0FKEA" 0603_HV 76.1,110.4 r270 top value=75.0k
R114 "CRCW060349K9FKEA" 0603_HV 57.5,80.8 r180 top value=49.9k
R115 "CRCW060349K9FKEA" 0603_HV 57.5,82.4 r180 top value=49.9k
R116 "CRCW060349K9FKEA" 0603_HV 57.5,84 r180 top value=49.9k
R117 "CRCW06031M00JNEA" 0603_HV 71.3,110.4 r270 top value=1.0Meg
R118 "CRCW06030000Z0EA" 0603_HV 51.2,84.5 r90 top value=0
R119 "CRCW06030000Z0EA" 0603_HV 49.6,84.5 r90 top value=0
R120 "CRCW060310K0FKEA" 0603_HV 52.8,84.5 r270 top value=10.0k
R121 "CRCW060368K1FKEA" 0603_HV 80,109.5 r180 top value=68.1k
R122 "CRCW12061R69FKEA" 1206 57.5,87.4 r270 top value=1.69
R123 "CRCW06031K50FKEA" 0603_HV 79.1,97.6 r270 top value=1.50k
R124 "CRCW06030000Z0EA" 0603_HV 74.3,97.6 r270 top value=0
R125 "CRCW06031K50FKEA" 0603_HV 80.7,97.6 r270 top value=1.50k
R126 "CRCW060310K0FKEA" 0603_HV 80,99.9 r180 top value=10.0k
R127 "CRCW060310R0FKEA" 0603_HV 80,106.3 r0 top value=10.0
R128 "CRCW060320K5FKEA" 0603_HV 80,104.7 r0 top value=20.5k
R129 "CRCW06031K10FKEA" 0603_HV 80,103.1 r180 top value=1.10k
R130 "FCSL90R050FER" 3518_WIDE 200,56.5 r180 top value=0.05
R131 "CRCW060310K0FKEA" 0603_HV 202.8,67 r180 top value=10.0k
R201 "CRCW0603100RJNEA" 0603_HV 89.1,8.5 r270 top value=100
R202 "CRCW06030000Z0EA" 0603_HV 84.3,8.5 r90 top value=0
R203 "CRCW06030000Z0EA" 0603_HV 87.5,11.5 r90 top value=0
R204 "CRCW060310K0FKEA" 0603_HV 87.5,8.5 r270 top value=10.0k
R205 "CRCW060349K9FKEA" 0603_HV 85.9,8.5 r270 top value=49.9k
R206 "CRCW060349K9FKEA" 0603_HV 85.9,11.5 r270 top value=49.9k
R207 "MCT06030C2008FP500" 0603_HV 82.7,8.5 r270 top value=2.00
R208 "CRCW06032R49FKEA" 0603_HV 77.5,25.5 r270 top value=2.49
R209 "CRCW06032R49FKEA" 0603_HV 85.4,25.4 r270 top value=2.49
R210 "CRCW060310K0FKEA" 0603_HV 80.2,26.2 r0 top value=10.0k
R211 "CRCW060310K0FKEA" 0603_HV 87.7,26.2 r0 top value=10.0k
R212 "CRCW0603100RJNEA" 0603_HV 59.6,8.5 r270 top value=100
R213 "CRCW06030000Z0EA" 0603_HV 54.8,8.5 r90 top value=0
R214 "CRCW06030000Z0EA" 0603_HV 58,11.5 r90 top value=0
R215 "CRCW060310K0FKEA" 0603_HV 58,8.5 r270 top value=10.0k
R216 "CRCW060349K9FKEA" 0603_HV 56.4,8.5 r270 top value=49.9k
R217 "CRCW060349K9FKEA" 0603_HV 56.4,11.5 r270 top value=49.9k
R218 "MCT06030C2008FP500" 0603_HV 53.2,8.5 r270 top value=2.00
R219 "CRCW06032R49FKEA" 0603_HV 48,25.5 r270 top value=2.49
R220 "CRCW06032R49FKEA" 0603_HV 55.9,25.4 r270 top value=2.49
R221 "CRCW060310K0FKEA" 0603_HV 50.7,26.2 r0 top value=10.0k
R222 "CRCW060310K0FKEA" 0603_HV 58.2,26.2 r0 top value=10.0k
R301 "CRCW06030000Z0EA" 0603_HV 102,98.7 r0 top value=0
R302 "CRCW060310K0FKEA" 0603_HV 99,100.3 r180 top value=10.0k
R303 "CRCW060349K9FKEA" 0603_HV 99,101.9 r180 top value=49.9k
R304 "CRCW06030000Z0EA" 0603_HV 99,98.7 r0 top value=0
R305 "CRCW06030000Z0EA" 0603_HV 102,100.3 r0 top value=0
R306 "CRCW06030000Z0EA" 0603_HV 99,103.5 r0 top value=0
R307 "CRM2512-FX-1002ELF" FP-CRM2512-FX-1002ELF_2512-MFG 142,70.5 r90 top value=10k
R308 "CRM2512-FX-1002ELF" FP-CRM2512-FX-1002ELF_2512-MFG 148.5,70.5 r90 top value=10k
R309 "CRM2512-FX-1002ELF" FP-CRM2512-FX-1002ELF_2512-MFG 155,70.5 r90 top value=10k
R310 "CRCW06030000Z0EA" 0603_HV 102.7,109.683 r270 top value=0
R311 "CRM2512-FX-1002ELF" FP-CRM2512-FX-1002ELF_2512-MFG 161.5,70.5 r90 top value=10k
R312 "CRCW06032R49FKEA" 0603_HV 115,109.4 r270 top value=2.49
R313 "CRCW060310K0FKEA" 0603_HV 114.3,111.8 r180 top value=10.0k
R314 "352233RJT" FP-3522330KFT_2512-IPC_A 131,110 r0 top value=33
R315 "CRCW06032R49FKEA" 0603_HV 118.5,93.8 r180 top value=2.49
R316 "CRCW06032R49FKEA" 0603_HV 118.5,99.8 r180 top value=2.49
R317 "CRCW06032R49FKEA" 0603_HV 118.5,105.8 r180 top value=2.49
R318 "CRCW06032R49FKEA" 0603_HV 118.5,111.8 r180 top value=2.49
R319 "352233RJT" FP-3522330KFT_2512-IPC_A 131,104 r0 top value=33
R320 "CRCW060310K0FKEA" 0603_HV 118.5,92.2 r0 top value=10.0k
R321 "CRCW060310K0FKEA" 0603_HV 118.5,98.2 r0 top value=10.0k
R322 "CRCW060310K0FKEA" 0603_HV 118.5,104.2 r0 top value=10.0k
R323 "CRCW060310K0FKEA" 0603_HV 118.5,110.2 r0 top value=10.0k
R324 "352233RJT" FP-3522330KFT_2512-IPC_A 131,98 r0 top value=33
R325 "352233RJT" FP-3522330KFT_2512-IPC_A 131,92 r0 top value=33
R326 "CRCW06030000Z0EA" 0603_HV 102,23.7 r0 top value=0
R327 "CRCW060310K0FKEA" 0603_HV 99,25.3 r180 top value=10.0k
R328 "CRCW060349K9FKEA" 0603_HV 99,26.9 r180 top value=49.9k
R329 "CRCW06030000Z0EA" 0603_HV 99,23.7 r0 top value=0
R330 "CRCW06030000Z0EA" 0603_HV 102,25.3 r0 top value=0
R331 "CRCW06030000Z0EA" 0603_HV 99,28.5 r0 top value=0
R332 "CRM2512-FX-1002ELF" FP-CRM2512-FX-1002ELF_2512-MFG 142,56.5 r270 top value=10k
R333 "CRM2512-FX-1002ELF" FP-CRM2512-FX-1002ELF_2512-MFG 148.5,56.5 r270 top value=10k
R334 "CRM2512-FX-1002ELF" FP-CRM2512-FX-1002ELF_2512-MFG 155,56.5 r270 top value=10k
R335 "CRCW06030000Z0EA" 0603_HV 100.3,31.5 r90 top value=0
R336 "CRM2512-FX-1002ELF" FP-CRM2512-FX-1002ELF_2512-MFG 161.5,56.5 r270 top value=10k
R337 "CRCW06032R49FKEA" 0603_HV 115,34.4 r270 top value=2.49
R338 "CRCW060310K0FKEA" 0603_HV 114.3,36.8 r180 top value=10.0k
R339 "352233RJT" FP-3522330KFT_2512-IPC_A 131,37 r0 top value=33
R340 "CRCW06032R49FKEA" 0603_HV 118.5,18.8 r180 top value=2.49
R341 "CRCW06032R49FKEA" 0603_HV 118.5,24.8 r180 top value=2.49
R342 "CRCW06032R49FKEA" 0603_HV 118.5,30.8 r180 top value=2.49
R343 "CRCW06032R49FKEA" 0603_HV 118.5,36.8 r180 top value=2.49
R344 "352233RJT" FP-3522330KFT_2512-IPC_A 131,31 r0 top value=33
R345 "CRCW060310K0FKEA" 0603_HV 118.5,17.2 r0 top value=10.0k
R346 "CRCW060310K0FKEA" 0603_HV 118.5,23.2 r0 top value=10.0k
R347 "CRCW060310K0FKEA" 0603_HV 118.5,29.2 r0 top value=10.0k
R348 "CRCW060310K0FKEA" 0603_HV 118.5,35.2 r0 top value=10.0k
R349 "352233RJT" FP-3522330KFT_2512-IPC_A 131,19 r0 top value=33
R350 "352233RJT" FP-3522330KFT_2512-IPC_A 131,25 r0 top value=33
T101 "63554-R01" FP-63554-R01_SMT_XFRMR_24MM0_20MM0-MFG 36.5,66.5 r90 top
T102 "63554-R01" FP-63554-R01_SMT_XFRMR_24MM0_20MM0-MFG 57.5,66.5 r90 top
T103 "64191R00" FP-64191R00_PTH_XFRMR_55MM0_48MM0-MFG 102.5,64.5 r0 top
TP101 "5010" Keystone5010 5,92 r0 top
TP102 "5011" Keystone5011 5,31 r0 top
TP103 "TP_SM_1MM" TP_SM_1MM 196,54.5 r90 top
TP104 "5010" Keystone5010 197,93.5 r0 top
TP105 "5011" Keystone5011 197,32.5 r0 top
U101 "TPS7H5005MPWSEP" PW0024A-MFG 73.5,103.9 r270 top
U201 "TPS7H6005/EM" DCA0056M-MFG 82.7,18.5 r90 top
U202 "TPS7H6005/EM" DCA0056M-MFG 53.2,18.5 r90 top
U301 "TPS7H6005/EM" DCA0056M-MFG 109,103.5 r0 top
U302 "TPS7H6005/EM" DCA0056M-MFG 109,28.5 r0 top

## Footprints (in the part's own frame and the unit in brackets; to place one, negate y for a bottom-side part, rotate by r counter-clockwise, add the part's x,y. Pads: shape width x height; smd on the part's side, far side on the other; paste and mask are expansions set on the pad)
0603_HV [mil] "Ernesto recommended land pattern.  26 mil between pads."
  rect 30x30 smd: 1(-28,0) 2(28,0)
  silkscreen extent -52,-24 52,24, body extent -34,-19 34,19, height 39
0805_HV [mil] "0805 with 30mil clearance between pads"
  rect 50x63 smd: 1(-40,0) 2(40,0)
  silkscreen extent -74,-40 74,40, body extent -43,-29 43,29, height 57
1206 [mm] "1206 from SM-752 data"
  rect 1.3x1.85 smd: 1(-1.45,0) 2(1.45,0)
  silkscreen extent -2.4,-1.21 2.4,1.21, body extent -1.7,-0.9 1.7,0.9, height 1.35
1206_180 [mm] "1206_180"
  rect 1.1x1.6 smd: 1(-1.7,0) 2(1.7,0)
  silkscreen extent -0.9,-1 0.9,1, body extent -1.75,-0.95 1.75,0.95, height 1.8
1210_280 [mm] "SMD, 2-Leads, Body 3.6x2.8mm, Height 2.8mm"
  rect 1.1x2.2 smd: 1(-1.65,0) 2(1.65,0)
  silkscreen extent -0.84,-1.4 0.84,1.4, body extent -1.8,-1.4 1.8,1.4, height 2.8
1812_280 [mm] "1812"
  rect 1.6x3.4 smd: 1(-2,0) 2(2,0)
  silkscreen extent -0.8,-1.6 0.8,1.6, body extent -2.4,-1.7 2.4,1.7, height 2.8
2512_WIDE_VISHAY [mm] "Vishay recommended land pattern"
  rect 1.9x7.6 smd: 1(-1.55,0) 2(1.55,0)
  silkscreen extent -0.3,-3.32 0.3,3.35, body extent -1.7,-3.25 1.7,3.25, height 0.9
3518_WIDE [mm] "Ohmite recommended land pattern"
  rect 1x9.2 smd: 1(-2.05,0) 2(2.05,0)
  silkscreen extent -1.25,-4.6 1.25,4.6, body extent -2.35,-4.55 2.35,4.55, height 0.7
7360-38 [mm] "Medium density IPC, based on Kemet T495 series dimension data"
  rect 2.55x4.15 smd: 1(-3.025,0) 2(3.025,0)
  silkscreen extent -4.35,-3.2 3.8,3.2, body extent -3.8,-3.15 3.8,3.15, height 3.8
DCA0056M-MFG [mm]
  rrect33% 1.55x0.3 smd paste+0 mask+0: 1(-3.75,6.75) 2(-3.75,6.25) 3(-3.75,5.75) 4(-3.75,5.25) 5(-3.75,4.75) 6(-3.75,4.25) 7(-3.75,3.75) 8(-3.75,3.25) 9(-3.75,2.75) 10(-3.75,2.25) 11(-3.75,1.75) 12(-3.75,1.25) 13(-3.75,0.75) 14(-3.75,0.25) 15(-3.75,-0.25) 16(-3.75,-0.75) 17(-3.75,-1.25) 18(-3.75,-1.75) 19(-3.75,-2.25) 20(-3.75,-2.75) 21(-3.75,-3.25) 22(-3.75,-3.75) 23(-3.75,-4.25) 24(-3.75,-4.75) 25(-3.75,-5.25) 26(-3.75,-5.75) 27(-3.75,-6.25) 28(-3.75,-6.75) 29(3.75,-6.75) 30(3.75,-6.25) 31(3.75,-5.75) 32(3.75,-5.25) 33(3.75,-4.75) 34(3.75,-4.25) 35(3.75,-3.75) 36(3.75,-3.25) 37(3.75,-2.75) 38(3.75,-2.25) 39(3.75,-1.75) 40(3.75,-1.25) 41(3.75,-0.75) 42(3.75,-0.25) 43(3.75,0.25) 44(3.75,0.75) 45(3.75,1.25) 46(3.75,1.75) 47(3.75,2.25) 48(3.75,2.75) 49(3.75,3.25) 50(3.75,3.75) 51(3.75,4.25) 52(3.75,4.75) 53(3.75,5.25) 54(3.75,5.75) 55(3.75,6.25) 56(3.75,6.75)
  rrect2% 5.1x6.75 smd paste-1000 mask-1000: 57(0,3.625) 58(0,-3.625)
  silkscreen extent -5.22,-7.42 3.1,7.42, body extent -4.62,-7.15 4.62,7.15, height 0.25
EB_K16 [mm] "Panasonic"
  rect 7.5x2.5 smd: 1(-6.75,0) 2(6.75,0)
  silkscreen extent -9.6,-9.6 9.6,9.6, body extent -9.6,-9.6 9.6,9.6, height 17.01
FP-1212VS-111MED_SMT_IND_11MM5_12MM0-MFG [mm] "Recommended Land Pattern"
  rrect3% 3.3x10.34 smd paste+0 mask+0: 1(-4.42,-1.465) 2(4.42,-1.465)
  silkscreen extent -5.75,-6 5.75,6, body extent -6.17,-6.74 6.17,6.1, height 0.25
FP-63554-R01_SMT_XFRMR_24MM0_20MM0-MFG [mm]
  rrect3% 3.6x3.6 smd paste+0 mask+0: 1(-9.75,3.81) 2(-9.75,-3.81)
  rrect3% 3x3 smd paste+0 mask+0: 3(10.05,-6.35) 4(10.05,6.35)
  silkscreen extent -12.72,-10 12,10, body extent -12.1,-10.1 12.1,10.1, height 0.25
FP-64191R00_PTH_XFRMR_55MM0_48MM0-MFG [mm] "Recommended Land Pattern"
  rrect3% 3.2x3.2 hole 2.1 paste-2539.97 mask+0: 1(-25,8)
  round 3.2 hole 2.1 paste-2539.97 mask+0: 2(-25,-10) 3(25,-10.5) 3(25,-7) 4(25,5) 4(25,8.5)
  round 3.3 hole 3.3 unplated paste-2539.97 mask+0: ""(-6,-20.5) ""(-6,20.5) ""(6,-20.5) ""(6,20.5)
  silkscreen extent -28.12,-24 27.5,24, body extent -27.5,-24 27.5,24, height 15
FP-64192R00_PTH_IND_48MM0_33MM0-MFG [mm] "Recommended Land Pattern"
  rect 3.2x3.2 hole 2.1 paste-2539.97 mask+0: 1(-21.8,7) 2(-21.8,-10) 2(-21.8,-7)
  rrect3% 3.2x3.2 hole 2.1 paste-2539.97 mask+0: 1(-21.8,10)
  silkscreen extent -24,-16.5 24,16.5, body extent -24.02,-16.5 23.98,16.5, height 13
FP-3522330KFT_2512-IPC_A [mm]
  rrect4% 2.658x3.458 smd paste+0 mask+0: 1(-2.452,0) 2(2.452,0)
  silkscreen extent -0.82,-1.73 0.82,1.73, body extent -4.28,-2.23 4.28,2.23, height 0.25
FP-BAT46GWJ_SOD-123-MFG [mm]
  rrect11% 0.91x1.22 smd paste-1000 mask+0: 1(-1.635,0) 2(1.635,0)
  silkscreen extent -2.82,-0.85 0.8,0.85, body extent -2.29,-1.05 2.29,1.05, height 0.25
FP-CRM2512-FX-1002ELF_2512-MFG [mm]
  rrect4% 2.45x3.7 smd paste+0 mask+0: 1(-2.575,0) 2(2.575,0)
  silkscreen extent -0.97,-1.65 0.97,1.65, body extent -3.9,-1.95 3.9,1.95, height 0.25
FP-EPC2088_LGA8-MFG [mm]
  rrect52% 0.23x0.755 smd paste+0 mask+0: 1(-1.5,0.512) 2(-1.5,-0.512)
  rrect52% 0.23x1.605 smd paste-1000 mask+0: 3(-1,0) 5(0,0) 7(1,0)
  rrect52% 0.23x1.78 smd paste-1000 mask+0: 4(-0.5,0) 6(0.5,0) 8(1.5,0)
  silkscreen extent -1.99,-1.26 1.99,1.86, body extent -2.26,-1.49 2.26,1.49, height 0.25
FP-EPC2215_LGA6-MFG [mm]
  rrect44% 0.275x0.45 smd paste+0 mask+0: 1(-2,0.5)
  rrect44% 0.275x0.7 smd paste+0 mask+0: 2(-2,-0.375)
  rrect44% 0.275x1.21 smd paste+0 mask+0: 3(-1,0) 5(1,0)
  rrect44% 0.275x1.45 smd paste+0 mask+0: 4(0,0) 6(2,0)
  silkscreen extent -2.51,-0.81 2.51,1.41, body extent -2.82,-1.32 2.82,1.32, height 0.25
FP-SS1H20LW_SOD-123W-MFG [mm]
  rrect8% 1.2x1.4 smd paste+0 mask+0: 1(-1.55,0) 2(1.55,0)
  silkscreen extent -2.82,-0.95 0.58,0.95, body extent -2.25,-1.05 2.25,1.05, height 0.25
FP-SSQ-102-02-G-D_CONN_RCPT_4-MFG [mm] "Recommended Land Pattern"
  rrect6% 1.57x1.57 hole 1.02 paste-2539.97 mask+0: 1(1.27,-1.27)
  round 1.57 hole 1.02 paste-2539.97 mask+0: 2(1.27,1.27) 3(-1.27,-1.27) 4(-1.27,1.27)
  silkscreen extent -2.92,-3.15 2.92,2.54, body extent -2.79,-2.48 2.79,2.48, height 8.64
IEC_Caution_Small [mm]
  silkscreen extent -2.72,-2.36 2.72,2.35
IEC_HighVoltage_Medium [mm]
  silkscreen extent -5.51,-4.46 5.51,5.09
IEC_HotSurface_Medium [mm]
  silkscreen extent -5.51,-4.76 5.51,4.78
Keystone5010 [mil] "Keystone Multipurpose loops"
  round 87 hole 63: 1(0,0)
  silkscreen extent -70,-70 70,70, body extent -63,-63 63,62, height 319
Keystone5011 [mil] "Keystone Multipurpose loops"
  round 87 hole 63: 1(0,0)
  silkscreen extent -70,-70 70,70, body extent -63,-63 63,62, height 319
KEYSTONE_4820 [mm] "HEX NYLON STANDOFF 6-32, M-F 1\""
  round 0.025 on Mech3: 0(0,0)
  round 3.7 hole 3.6 unplated: MH(0,0)
  silkscreen extent -3.67,-3.67 3.67,3.67, body extent -3.67,-3.17 3.67,3.18, height 25.42
KTT0002A-MFG [mm]
  rrect10% 1.05x3.82 smd paste+0 mask+0: 1(-2.54,-7.755) 3(2.54,-7.755)
  rrect1% 8.55x7.48 smd paste-1000 mask+0: 4(0,2.545)
  silkscreen extent -5.13,-4.62 5.13,4.62, body extent -5.23,-9.76 5.23,6.39, height 0.25
On-Shore_ED120_2DS [mm] "ONSHORE"
  rrect5% 2x2 hole 1.25: 1(-2.54,0)
  round 2 hole 1.25: 2(2.54,0)
  silkscreen extent -5.6,-4 5.12,5, body extent -5.78,-4 5.08,5, height 13
Panduit_CXS70-14-C [mil] "Panduit"
  rect 770x500 hole 270 copper offset -74.8,0 paste-99999: 1(0,0)
  body extent -960,-250 310,250, height 684
PW0024A-MFG [mm]
  rrect22% 1.5x0.45 smd paste+0 mask+0: 1(-2.9,3.575) 2(-2.9,2.925) 3(-2.9,2.275) 4(-2.9,1.625) 5(-2.9,0.975) 6(-2.9,0.325) 7(-2.9,-0.325) 8(-2.9,-0.975) 9(-2.9,-1.625) 10(-2.9,-2.275) 11(-2.9,-2.925) 12(-2.9,-3.575) 13(2.9,-3.575) 14(2.9,-2.925) 15(2.9,-2.275) 16(2.9,-1.625) 17(2.9,-0.975) 18(2.9,-0.325) 19(2.9,0.325) 20(2.9,0.975) 21(2.9,1.625) 22(2.9,2.275) 23(2.9,2.925) 24(2.9,3.575)
  silkscreen extent -4.37,-3.95 1.78,3.95, body extent -3.75,-4.2 3.75,4.2, height 0.25
SMB [mm] "Molded Diode, 2-Leads, Body 5.4x3.6mm, IPC Medium Density, based on OnSemi component dimensions"
  rect 2.159x2.743 smd: 1(-2.21,0) 2(2.21,0)
  silkscreen extent -3.94,-2.08 3.17,2.08, body extent -2.7,-1.8 2.7,1.8, height 2.32
SOD-123 [mm] "On Semi recommended land pattern"
  rect 0.915x1.22 smd: 1(-1.637,0) 2(1.637,0)
  silkscreen extent -2.74,-1.17 2.03,1.17, body extent -1.93,-0.9 1.93,0.9, height 1.35
SOT-363 [mm]
  rect 0.6x0.42 smd mask+0.051: 1(-0.95,0.65) 2(-0.95,0) 3(-0.95,-0.65) 4(0.95,-0.65) 5(0.95,0) 6(0.95,0.65)
  silkscreen extent -0.38,-1.02 0.38,1.02, body extent -1.1,-1.1 1.1,1.1, height 1.12
TP_SM_1MM [mm] "1mm Test Point, SMT"
  round 1 smd paste-0.5: 1(0,0)
WURTH_61300211121 [mm] "Header, 2.54mm, 2x1, TH"
  rrect50% 1.65x1.65 hole 1.15: 1(-1.27,0)
  round 1.65 hole 1.15: 2(1.27,0)
  body extent -2.54,-1.27 2.54,1.27, height 8.54
WURTH_61300311121 [mm] "Header, 2.54mm, 3x1, TH"
  rrect50% 1.65x1.65 hole 1.15: 1(-2.54,0)
  round 1.65 hole 1.15: 2(0,0) 3(2.54,0)
  body extent -3.81,-1.27 3.81,1.27, height 8.54
WURTH_61300611121 [mm] "Header, 2.54mm, 6x1, TH"
  rrect50% 1.65x1.65 hole 1.15: 1(-6.35,0)
  round 1.65 hole 1.15: 2(-3.81,0) 3(-1.27,0) 4(1.27,0) 5(3.81,0) 6(6.35,0)
  body extent -7.62,-1.27 7.62,1.27, height 8.54

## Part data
C101 C102: library part CMP-0011430-2, "CAP, AL, 47 uF, 200 V, +/- 20%, SMD", Cap_Case=18x16.5, Manufacturer=Panasonic, Supplier Part Number 1=PCE3584CT-ND, Tolerance_%=20%, Value1=Unknown, Value2=200V, ValueDisplayed=47uF
C103 C105: library part CMP-0081058-1, "CAP, CERM, 1 µF, 200 V,+/- 10%, X7R, 1812", Cap_Case=1812_280, Manufacturer=AVX, Supplier Part Number 1=478-10705-1-ND, TempCo=X7R, Tolerance_%=10%, Value2=200V, ValueDisplayed=1µF
C104 C202 C203 C205 C208 C209 C211 C301 C302 C308 C309: library part CMP-0007405-5, "CAP, CERM, 1 uF, 25 V, +/- 10%, X7R, 0603", Cap_Case=0603, Manufacturer=MuRata, Supplier Part Number 1=490-5307-1-ND, TempCo=X7R, Tolerance_%=10%, Value1=Unknown, Value2=25V, ValueDisplayed=1uF
C106 C206 C212 C304 C306 C311 C313: library part CMP-0007499-4, "CAP, CERM, 2.2 uF, 16 V, +/- 10%, X7R, 0603", Cap_Case=0603, Manufacturer=MuRata, Supplier Part Number 1=81-GRM188Z71C225KE3D, TempCo=X7R, Tolerance_%=10%, Value1=Unknown, Value2=16V, ValueDisplayed=2.2uF
C107 C108: library part CMP-0008972-2, "CAP, CERM, 0.1 uF, 200 V, +/- 10%, X7R, 1206", Cap_Case=3.2x16x16mm, Manufacturer=MuRata, Supplier Part Number 1=490-13379-1-ND, TempCo=X7R, Tolerance_%=10%, Value1=Unknown, Value2=200V, ValueDisplayed=0.1uF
